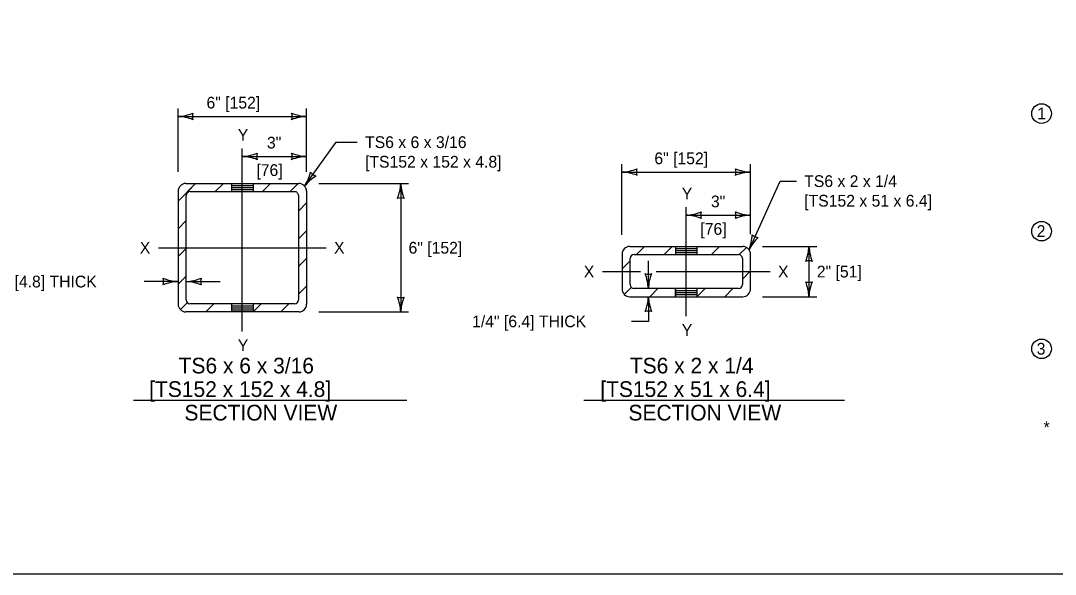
# Model space of a CAD drawing. Extents: x 49991.4 to 50021, y 49987.6 to 50011.4.
# Drawn here: x 50005.86 to 50011.14, y 49987.8 to 49990.62 of the extents above; entities that cross this region are included whole.
import ezdxf

# ---------------------------------------------------------------- set-up
doc = ezdxf.new("R2010")
doc.units = 0
for name, color, linetype in [('Level 1', 7, 'Continuous'), ('Level 2', 7, 'Continuous'), ('Level 3', 7, 'Continuous'), ('Level 4', 7, 'Continuous'), ('Level 5', 7, 'Continuous')]:
    doc.layers.add(name, color=color, linetype=linetype)

msp = doc.modelspace()

# ---------------------------------------------------------------- linework, layer by layer
at = {"layer": 'Level 1'}
for p, q in [((50006.6662, 49989.7029), (50006.7358, 49989.7725)), ((50006.6662, 49989.7524), (50006.6662, 49989.1772)), ((50006.7062, 49989.7924), (50007.2813, 49989.7924)), ((50006.7142, 49989.7509), (50006.7557, 49989.7924)), ((50006.7276, 49989.751), (50007.2599, 49989.751)), ((50006.8557, 49989.751), (50006.8971, 49989.7924)), ((50006.9388, 49989.7815), (50007.0482, 49989.7815)), ((50006.9388, 49989.7715), (50007.0482, 49989.7715)), ((50006.9388, 49989.7615), (50007.0482, 49989.7615)), ((50007.0964, 49989.751), (50007.1378, 49989.7924)), ((50007.2378, 49989.751), (50007.2792, 49989.7924)), ((50007.3213, 49989.7524), (50007.3213, 49989.1771)), ((50006.7076, 49989.1985), (50006.7076, 49989.731)), ((50007.2799, 49989.7309), (50007.2799, 49989.1986)), ((50007.2799, 49989.6516), (50007.3213, 49989.693)), ((50006.6662, 49989.5614), (50006.7076, 49989.6028)), ((50007.2799, 49989.5102), (50007.3213, 49989.5516)), ((50006.6662, 49989.42), (50006.7076, 49989.4614)), ((50008.9692, 49989.4712), (50009.5443, 49989.4712)), ((50009.0025, 49989.4298), (50009.0439, 49989.4712)), ((50009.1439, 49989.4298), (50009.1853, 49989.4712)), ((50009.2019, 49989.4605), (50009.3113, 49989.4605)), ((50009.2019, 49989.4505), (50009.3113, 49989.4505)), ((50009.2019, 49989.4405), (50009.3113, 49989.4405)), ((50009.3847, 49989.4298), (50009.4261, 49989.4712)), ((50009.5259, 49989.4295), (50009.5629, 49989.4665)), ((50007.2799, 49989.3688), (50007.3213, 49989.4102)), ((50008.9292, 49989.4312), (50008.9292, 49989.255)), ((50008.9292, 49989.3564), (50008.9706, 49989.3978)), ((50008.9706, 49989.2764), (50008.9706, 49989.4098)), ((50008.9906, 49989.4298), (50009.5229, 49989.4298)), ((50009.5429, 49989.4098), (50009.5429, 49989.2764)), ((50009.5843, 49989.255), (50009.5843, 49989.4312)), ((50009.5429, 49989.3051), (50009.5843, 49989.3465)), ((50006.6662, 49989.2786), (50006.7076, 49989.32)), ((50007.2799, 49989.2274), (50007.3213, 49989.2688)), ((50008.9409, 49989.2267), (50008.9764, 49989.2622)), ((50009.5229, 49989.2564), (50008.9899, 49989.2564)), ((50009.0706, 49989.215), (50009.112, 49989.2564)), ((50009.2019, 49989.2457), (50009.3113, 49989.2457)), ((50009.2019, 49989.2357), (50009.3113, 49989.2357)), ((50009.2019, 49989.2257), (50009.3113, 49989.2257)), ((50009.3113, 49989.215), (50009.3527, 49989.2564)), ((50009.4528, 49989.215), (50009.4942, 49989.2564)), ((50006.6779, 49989.1489), (50006.7134, 49989.1844)), ((50006.7075, 49989.1785), (50006.7075, 49989.1785)), ((50007.2599, 49989.1786), (50006.7262, 49989.1786)), ((50006.8076, 49989.1372), (50006.849, 49989.1786)), ((50007.0482, 49989.1372), (50007.0896, 49989.1786)), ((50007.1897, 49989.1372), (50007.2311, 49989.1786)), ((50008.9692, 49989.215), (50009.5443, 49989.215)), ((50007.2833, 49989.1372), (50006.7062, 49989.1372)), ((50006.9388, 49989.1678), (50007.0482, 49989.1678)), ((50006.9388, 49989.1578), (50007.0482, 49989.1578)), ((50006.9388, 49989.1478), (50007.0482, 49989.1478))]:
    msp.add_line(p, q, dxfattribs=at)
msp.add_lwpolyline([(49999.3835, 49998.9992), (50016.7501, 49998.9992), (50016.7501, 49987.7988), (49999.3835, 49987.7988)], close=True, dxfattribs=at)
for centre, radius, start, end in [((50006.7062, 49989.7524), 0.04, 90, 180), ((50006.7276, 49989.731), 0.02, 90, 180), ((50007.2599, 49989.731), 0.02, 359.8581, 90), ((50007.2813, 49989.7524), 0.04, 0, 90), ((50008.9692, 49989.4312), 0.04, 90, 180), ((50009.5443, 49989.4312), 0.04, 0, 90), ((50008.9906, 49989.4098), 0.02, 90, 179.9618), ((50009.5229, 49989.4098), 0.02, 0, 90), ((50008.9906, 49989.2764), 0.02, 180, 270), ((50009.5229, 49989.2764), 0.02, 270, 360), ((50008.9692, 49989.255), 0.04, 180, 270), ((50009.5443, 49989.255), 0.04, 270, 360), ((50006.7062, 49989.1772), 0.04, 180, 270), ((50006.7276, 49989.1985), 0.02, 180, 265.9668), ((50007.2599, 49989.1986), 0.02, 270, 0), ((50007.2813, 49989.1772), 0.04, 272.8516, 0)]:
    msp.add_arc(centre, radius, start, end, dxfattribs=at)
at = {"layer": 'Level 2'}
for p, q in [((50006.439, 49988.6878), (50007.8329, 49988.6878)), ((50008.7339, 49988.6875), (50010.0634, 49988.6875))]:
    msp.add_line(p, q, dxfattribs=at)
for centre in [(50011.0678, 49990.1491), (50011.0678, 49989.5491), (50011.0678, 49988.9491)]:
    msp.add_circle(centre, 0.05, dxfattribs=at)
at = {"layer": 'Level 3'}
for p, q in [((50006.666, 49989.8523), (50006.666, 49990.1747)), ((50007.3213, 49989.8523), (50007.3213, 49990.1747)), ((50006.666, 49990.1347), (50007.3211, 49990.1347)), ((50007.3114, 49989.7786), (50007.4721, 49990.0032)), ((50007.4721, 49990.0032), (50007.5794, 49990.0032)), ((50006.9935, 49989.9307), (50007.3211, 49989.9307)), ((50008.9291, 49989.5311), (50008.9291, 49989.8908)), ((50009.5842, 49989.5335), (50009.5842, 49989.8908)), ((50008.9291, 49989.8508), (50009.5842, 49989.8508)), ((50009.5767, 49989.4545), (50009.7356, 49989.8044)), ((50009.7356, 49989.8044), (50009.818, 49989.8044)), ((50007.3836, 49989.7923), (50007.8411, 49989.7923)), ((50007.8011, 49989.7923), (50007.8011, 49989.1372)), ((50009.2566, 49989.6308), (50009.5842, 49989.6308)), ((50009.6459, 49989.4711), (50009.9222, 49989.4711)), ((50009.8822, 49989.4711), (50009.8822, 49989.215)), ((50009.0634, 49989.2564), (50009.0634, 49989.3973)), ((50006.6662, 49989.2921), (50006.4928, 49989.2921)), ((50006.7076, 49989.2921), (50006.881, 49989.2921)), ((50009.0634, 49989.215), (50009.0634, 49989.089)), ((50009.6451, 49989.215), (50009.9222, 49989.215)), ((50007.3836, 49989.1372), (50007.8411, 49989.1372)), ((50009.0634, 49989.089), (50008.9782, 49989.089))]:
    msp.add_line(p, q, dxfattribs=at)
for centre, radius, start, end in [((50006.6545, 49990.3674), 0.233, 272.8273, 292.0772), ((50006.6568, 49989.9126), 0.2223, 67.456, 87.6395), ((50006.7942, 49990.1347), 0.0548, 162.1388, 197.8612), ((50007.3302, 49990.3569), 0.2223, 247.456, 267.6395), ((50007.1929, 49990.1347), 0.0548, 342.1388, 17.8612), ((50007.3326, 49989.902), 0.233, 92.8273, 112.0772), ((50006.982, 49990.1634), 0.233, 272.8273, 292.0772), ((50006.9843, 49989.7085), 0.2223, 67.456, 87.6395), ((50007.1217, 49989.9307), 0.0548, 162.1388, 197.8612), ((50007.3302, 49990.1528), 0.2223, 247.456, 267.6395), ((50007.1929, 49989.9307), 0.0548, 342.1388, 17.8612), ((50007.3326, 49989.698), 0.233, 92.8273, 112.0772), ((50008.9176, 49990.0836), 0.233, 272.8273, 292.0772), ((50009.0573, 49989.8508), 0.0548, 162.1388, 197.8612), ((50009.5934, 49990.073), 0.2223, 247.456, 267.6395), ((50009.456, 49989.8508), 0.0548, 342.1388, 17.8612), ((50007.1155, 49989.9047), 0.233, 327.244, 346.4938), ((50007.4867, 49989.6419), 0.2223, 121.8727, 142.0562), ((50007.386, 49989.8829), 0.0548, 216.5555, 252.2779), ((50008.92, 49989.6287), 0.2223, 67.456, 87.6395), ((50009.5957, 49989.6181), 0.233, 92.8273, 112.0772), ((50007.579, 49989.8015), 0.2223, 337.456, 357.6395), ((50008.0338, 49989.8038), 0.233, 182.8273, 202.0772), ((50007.8011, 49989.6641), 0.0548, 72.1388, 107.8612), ((50009.2451, 49989.8636), 0.233, 272.8273, 292.0772), ((50009.3848, 49989.6308), 0.0548, 162.1388, 197.8612), ((50009.5934, 49989.853), 0.2223, 247.456, 267.6395), ((50009.456, 49989.6308), 0.0548, 342.1388, 17.8612), ((50009.2475, 49989.4087), 0.2223, 67.456, 87.6395), ((50009.5957, 49989.3981), 0.233, 92.8273, 112.0772), ((50009.3601, 49989.5403), 0.233, 338.4003, 357.6502), ((50009.7752, 49989.3543), 0.2223, 133.029, 153.2126), ((50009.6298, 49989.5713), 0.0548, 227.7119, 263.4342), ((50009.6601, 49989.4803), 0.2223, 337.456, 357.6395), ((50010.115, 49989.4826), 0.233, 182.8273, 202.0772), ((50009.8822, 49989.3429), 0.0548, 72.1388, 107.8612), ((50009.0634, 49989.3846), 0.0548, 252.1388, 287.8612), ((50008.8307, 49989.2449), 0.233, 2.8273, 22.0772), ((50009.2855, 49989.2472), 0.2223, 157.456, 177.6395), ((50006.6753, 49989.5142), 0.2223, 247.456, 267.6395), ((50006.538, 49989.2921), 0.0548, 342.1388, 17.8612), ((50006.6777, 49989.0594), 0.233, 92.8273, 112.0772), ((50006.6961, 49989.5248), 0.233, 272.8273, 292.0772), ((50006.6984, 49989.0699), 0.2223, 67.456, 87.6395), ((50006.8358, 49989.2921), 0.0548, 162.1388, 197.8612), ((50009.8822, 49989.3432), 0.0548, 252.1388, 287.8612), ((50009.6495, 49989.2035), 0.233, 2.8273, 22.0772), ((50010.1044, 49989.2058), 0.2223, 157.456, 177.6395), ((50007.8011, 49989.2655), 0.0548, 252.1388, 287.8612), ((50007.5684, 49989.1257), 0.233, 2.8273, 22.0772), ((50008.0232, 49989.1281), 0.2223, 157.456, 177.6395), ((50008.8412, 49989.2241), 0.2223, 337.456, 357.6395), ((50009.2961, 49989.2265), 0.233, 182.8273, 202.0772), ((50009.0634, 49989.0867), 0.0548, 72.1388, 107.8612)]:
    msp.add_arc(centre, radius, start, end, dxfattribs=at)
at = {"layer": 'Level 4'}
for p, q in [((50006.9388, 49989.7924), (50006.9388, 49989.751)), ((50007.0482, 49989.7924), (50007.0482, 49989.751)), ((50009.2019, 49989.4712), (50009.2019, 49989.4298)), ((50009.3113, 49989.4712), (50009.3113, 49989.4298)), ((50009.2019, 49989.215), (50009.2019, 49989.2564)), ((50009.2019, 49989.2564), (50009.2019, 49989.215)), ((50009.3113, 49989.2564), (50009.3113, 49989.215)), ((50006.9388, 49989.1786), (50006.9388, 49989.1372)), ((50007.0482, 49989.1785), (50007.0482, 49989.1372))]:
    msp.add_line(p, q, dxfattribs=at)
at = {"layer": 'Level 5'}
for p, q in [((50006.9935, 49989.0371), (50006.9935, 49989.9707)), ((50009.2566, 49989.115), (50009.2566, 49989.6708)), ((50006.5662, 49989.4646), (50007.4213, 49989.4646)), ((50008.8292, 49989.343), (50009.0234, 49989.343)), ((50009.1034, 49989.343), (50009.6843, 49989.343))]:
    msp.add_line(p, q, dxfattribs=at)

# ---------------------------------------------------------------- texts
at = {"layer": 'Level 2'}
for s, height, p in [('6" [152]', 0.06, (50006.8111, 49990.1747)), ('1', 0.06, (50011.0456, 49990.1196)), ('Y', 0.06, (50006.9707, 49990.0107)), ('3"', 0.06, (50007.1193, 49989.9707)), ('TS6 x 6 x 3/16 ', 0.06, (50007.6194, 49989.9732)), ('[TS152 x 152 x 4.8]', 0.06, (50007.6194, 49989.8732)), ('6" [152]', 0.06, (50009.094, 49989.8908)), ('[76]', 0.06, (50007.0654, 49989.8307)), ('TS6 x 2 x 1/4', 0.06, (50009.858, 49989.7744)), ('Y', 0.06, (50009.2338, 49989.7108)), ('3"', 0.06, (50009.3824, 49989.6708)), ('[TS152 x 51 x 6.4]', 0.06, (50009.858, 49989.6744)), ('[76]', 0.06, (50009.3286, 49989.5308)), ('2', 0.06, (50011.043, 49989.5196)), ('X', 0.06, (50006.4711, 49989.4346)), ('X', 0.06, (50007.4613, 49989.4346)), ('6" [152]', 0.06, (50007.8411, 49989.4347)), ('X', 0.06, (50008.7342, 49989.313)), ('X', 0.06, (50009.7243, 49989.313)), ('2" [51]', 0.06, (50009.9222, 49989.313)), (' 3/16" [4.8] THICK', 0.06, (50005.6034, 49989.2621)), (' 1/4" [6.4] THICK', 0.06, (50008.1427, 49989.059)), ('Y', 0.06, (50009.2338, 49989.015)), ('Y', 0.06, (50006.9707, 49988.9371)), ('3', 0.06, (50011.043, 49988.9196)), ('TS6 x 6 x 3/16', 0.08, (50006.6692, 49988.8235)), ('TS6 x 2 x 1/4', 0.08, (50008.9691, 49988.8235)), ('[TS152 x 152 x 4.8]', 0.08, (50006.519, 49988.7035)), ('[TS152 x 51 x 6.4]', 0.08, (50008.8182, 49988.7035)), ('SECTION VIEW', 0.08, (50006.6988, 49988.5835)), ('SECTION VIEW', 0.08, (50008.962, 49988.5835)), ('*', 0.06, (50011.078, 49988.5191))]:
    msp.add_text(s, height=height, dxfattribs=at).set_placement(p)

doc.saveas('drawing.dxf')
